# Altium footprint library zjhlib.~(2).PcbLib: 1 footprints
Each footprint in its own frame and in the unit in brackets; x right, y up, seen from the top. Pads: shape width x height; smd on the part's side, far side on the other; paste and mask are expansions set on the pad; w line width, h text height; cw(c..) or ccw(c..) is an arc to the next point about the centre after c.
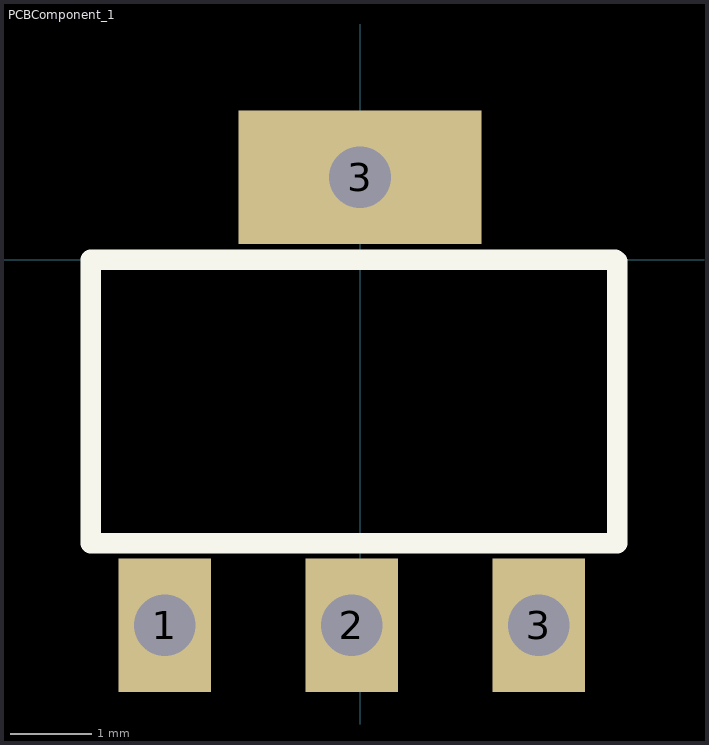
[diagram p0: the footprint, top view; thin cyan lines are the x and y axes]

## PCBComponent_1 [mm]
pads (4):
  rect 1.14x1.65 hole 0.762: 1(-2.413,-4.516) 2(-0.103,-4.516) 3(2.207,-4.516)
  rect 3x1.65 hole 0.762: 3(0,1.016)
Top Overlay:
  lines w0.254: 3.152,0 -3.325,0 -3.325,-3.5 3.175,-3.5 3.175,-0.023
